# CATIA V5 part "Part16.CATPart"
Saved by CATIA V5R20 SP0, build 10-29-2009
Part number: 8PF1242WB-00-20130117
Revision: ANY
Definition: UNKNOWN
Nomenclature: 8PF1242WB-00-20130117
Source: Unknown
Bounding box of the stored display mesh (mm): x 1756.092 to 1956.092, y 1456.713 to 1463.638, z 0 to 12
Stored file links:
  C:\Users\Utente\Desktop\IO LAVORO\3D X SITO CF\CUMSA\3D files PF\PF 1242WB\Part16.CATPart
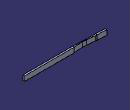
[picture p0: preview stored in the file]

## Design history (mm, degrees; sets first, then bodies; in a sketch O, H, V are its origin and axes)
Body1 "Cortar-Extruir1" (main body)
  Solid1: solid without history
